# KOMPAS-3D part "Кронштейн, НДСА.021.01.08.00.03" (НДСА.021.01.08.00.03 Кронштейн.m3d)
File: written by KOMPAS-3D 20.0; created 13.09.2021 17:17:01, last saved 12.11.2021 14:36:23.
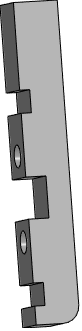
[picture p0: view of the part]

Document properties: Полное имя файла: C:\Users\korychko\Desktop\PLM\НДСА.021.01.08.00.03 Кронштейн.m3d

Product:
- Part/product: Кронштейн  | designation НДСА.021.01.08.00.03
    Материал: Д16  ГОСТ 4784-2019 (density 2800 kg/m3)
    Масса: 0.0369967
    additional columns: <item xmlns="http://appius.ru/pdm" xmlns:xs="http://www.w3.org/2001/XMLSchema" x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; <item xmlns="http://appius.ru/pdm" xmlns:xs="http://www.w3.org/2001/XMLSchema" x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; <item xmlns="http://appius.ru/pdm" xmlns:xs="http://www.w3.org/2001/XMLSchema" x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
    source file: НДСА.021.01.08.00.03 Кронштейн.cdw

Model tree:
1. Эскиз:1
2. Элемент выдавливания:1
     Расстояние 1 = 92
3. Эскиз:2  (with: Элемент выдавливания:1)
4. Элемент выдавливания:2
5. Смещенная плоскость:1
     Расстояние = 5.75
6. Сечение:1
7. Эскиз:6  (with: Элемент выдавливания:1)
8. Элемент выдавливания:6
9. Эскиз:7  (with: Элемент выдавливания:1, Элемент выдавливания:6)
10. Элемент выдавливания:7
     Расстояние 2 = 6
11. Эскиз:11  (with: Элемент выдавливания:1, Сечение:1)
12. Эскиз:12  (with: Элемент выдавливания:1, Элемент выдавливания:6)
13. Элемент выдавливания:12
14. Отверстие:1  (with: Элемент выдавливания:1, Сечение:1)  (labels: M5)
     Глубина выреза = 20; Диаметр отверстия = 4.13397; Угол конуса дна = 118; Расстояние 1 = 6.5; Расстояние 2 = 7
15. M5  (with: Элемент выдавливания:1)  (labels: cil0_24705-2004 coarse)
     Длина резьбы = 15; Шаг резьбы = 0.8; Номинальный диаметр резьбы = 5
16. Скругление:1  (with: Элемент выдавливания:1)
     Радиус = 5
17. Эскиз:13  (with: Элемент выдавливания:1)
18. Элемент выдавливания:13  (labels: Д16  ГОСТ 4784-2019)

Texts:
  НДСА.021.01.08.00.03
